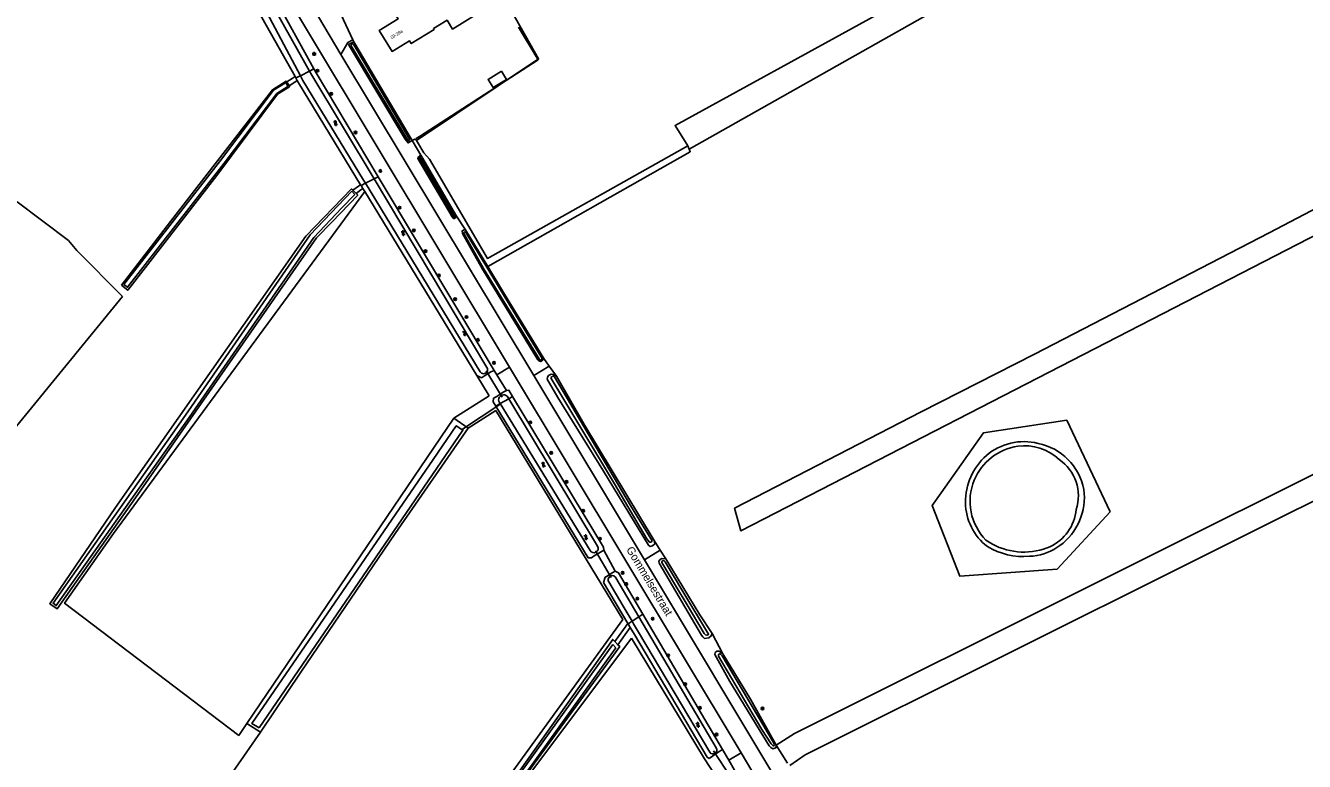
# Model space of a CAD drawing. Extents: x 137000 to 140001, y 403500 to 406000.
# Drawn here: x 138915.5 to 139315.1, y 404598.3 to 404828.4 of the extents above; entities that cross this region are included whole.
import ezdxf

# ---------------------------------------------------------------- set-up
doc = ezdxf.new("R2010")
doc.units = 0
for name, color, linetype in [('gg-afsc-draadraster', 7, 'Continuous'), ('gg-afsc-erfafscheiding', 7, 'Continuous'), ('gg-afsc-hekwerk', 7, 'Continuous'), ('gg-afsc-lijn draadraster', 7, 'Continuous'), ('gg-anno-huisnummerreeks BGT', 7, 'Continuous'), ('gg-anno-openbare ruimte label', 7, 'Continuous'), ('gg-bbg-hoofdgebouw', 7, 'Continuous'), ('gg-bbg-luifel en loopbrug', 7, 'Continuous'), ('gg-knt-bronhoudergrens', 7, 'Continuous'), ('gg-knt-onverhard', 7, 'Continuous'), ('gg-knt-verharding', 7, 'Continuous'), ('gg-knt-verharding nz', 7, 'Continuous'), ('gg-kntw-bovenkant insteek waterloop', 7, 'Continuous'), ('gg-kntw-waterlijn', 7, 'Continuous'), ('gg-kwrk-duiker nz buis', 7, 'Continuous'), ('gt-grn-groengrens', 7, 'Continuous'), ('gt-grn-groengrens NZ', 7, 'Continuous'), ('gt-grn-vlakafsluiter', 7, 'Continuous'), ('gt-grn-weggrens', 7, 'Continuous'), ('gt-symb-boom', 7, 'Continuous'), ('gt-symb-lichtmast', 7, 'Continuous'), ('gt-symb-watersymbool', 7, 'Continuous')]:
    doc.layers.add(name, color=color, linetype=linetype)

# ---------------------------------------------------------------- blocks, each defined once
blk = doc.blocks.new('gt0-BOOM')
at = {"layer": 'gt-symb-boom'}
for radius in [0.4, 0.2]:
    blk.add_circle((0, 0), radius, dxfattribs=at)
blk = doc.blocks.new('gt0-WA')
at = {"layer": 'gt-symb-watersymbool'}
for centre, start, end in [((-0.32, 0.02), 28.0725, 151.9275), ((0.43, 0.42), 208.0725, 331.9275), ((-0.32, -0.43), 28.0725, 151.9275), ((0.43, -0.03), 208.0725, 331.9275)]:
    blk.add_arc(centre, 0.425, start, end, dxfattribs=at)
blk = doc.blocks.new('gt0-LMAST')
at = {"layer": 'gt-symb-lichtmast'}
for p, q in [((-0.18, 0.17), (-0.45, 0.44)), ((-0.01, 0.25), (-0.01, 0.62)), ((0.17, 0.17), (0.44, 0.44)), ((-0.26, 0), (-0.63, 0)), ((-0.18, -0.18), (-0.45, -0.45)), ((-0.01, -0.25), (-0.01, -0.63)), ((0.44, -0.45), (0.17, -0.18)), ((0.24, 0), (0.62, 0))]:
    blk.add_line(p, q, dxfattribs=at)
blk.add_circle((-0.01, 0), 0.25, dxfattribs=at)

msp = doc.modelspace()

# ---------------------------------------------------------------- linework, layer by layer
at = {"layer": 'gg-afsc-draadraster'}
msp.add_line((138984.69, 404610.16), (138982.17, 404606.45), dxfattribs=at)
msp.add_lwpolyline([(139102.12, 404642.66), (139080.7, 404678.06), (139062.45, 404708.05)], dxfattribs=at)
at = {"layer": 'gg-afsc-erfafscheiding'}
for p, q in [((139018.1, 404823.32), (139017.74, 404823.94)), ((139103.71, 404641.47), (139099.63, 404635.81)), ((139104.48, 404640.16), (139100.63, 404634.79))]:
    msp.add_line(p, q, dxfattribs=at)
for points in [[(138999.75, 404812.46), (138998.86, 404811.88), (138997.11, 404810.74)], [(139000.44, 404811.23), (138999.62, 404810.7), (138997.86, 404809.56)], [(139020.22, 404778.64), (139019.51, 404778.14), (139017.76, 404776.88)]]:
    msp.add_lwpolyline(points, dxfattribs=at)
at = {"layer": 'gg-afsc-hekwerk'}
for p, q in [((139075.7, 404817.67), (139069.55, 404827.92)), ((139038.6, 404793.75), (139075.7, 404817.67)), ((139037.62, 404793.12), (139038.6, 404793.75))]:
    msp.add_line(p, q, dxfattribs=at)
at = {"layer": 'gg-afsc-lijn draadraster'}
for p, q in [((139049.39, 404705.6), (138984.69, 404610.16)), ((138984.69, 404610.16), (138982.17, 404606.45))]:
    msp.add_line(p, q, dxfattribs=at)
msp.add_lwpolyline([(139102.12, 404642.66), (139080.7, 404678.06), (139062.45, 404708.05)], dxfattribs=at)
at = {"layer": 'gg-bbg-hoofdgebouw'}
msp.add_lwpolyline([(139059.68, 404833.96), (139048.96, 404827.28), (139047.24, 404830.05), (139043, 404827.42), (139043.15, 404827.18), (139036.02, 404822.75), (139035.46, 404823.64), (139030.04, 404820.29), (139026.03, 404826.87), (139031.92, 404830.46), (139031.33, 404831.38), (139037.89, 404835.41), (139038.07, 404835.11), (139042.34, 404837.73)], dxfattribs=at)
at = {"layer": 'gg-bbg-luifel en loopbrug'}
msp.add_lwpolyline([(139064.22, 404814.11), (139060.04, 404811.56), (139061.6, 404809), (139065.78, 404811.55), (139064.22, 404814.11)], dxfattribs=at)
at = {"layer": 'gg-knt-bronhoudergrens'}
for p, q in [((139021.53, 404776.49), (138943, 404669.59)), ((139079.14, 404721.91), (139077.41, 404724.28)), ((139081.41, 404718.79), (139079.14, 404721.91)), ((139056.48, 404719.01), (139060.34, 404712.65)), ((139049.39, 404705.6), (139060.34, 404712.65)), ((139053.85, 404702.51), (139062.45, 404708.05)), ((139111.92, 404667.43), (139113.85, 404664.37)), ((139096.19, 404664.4), (139099.72, 404657.86)), ((139115.58, 404661.63), (139113.85, 404664.37)), ((139130.03, 404638.28), (139133.35, 404632.02)), ((139104.82, 404636.82), (139127.61, 404599.12)), ((139153.59, 404597.79), (139150.08, 404603.43))]:
    msp.add_line(p, q, dxfattribs=at)
for points in [[(139037.66, 404792.46), (139075.83, 404817.93), (139067.22, 404833.1), (139070.72, 404835.33), (139068.44, 404839.22), (139085.09, 404850.14), (139076.16, 404864.06), (139082.38, 404867.96), (139085.94, 404869.01), (139084.03, 404871.84), (139082.12, 404872.23), (139080.67, 404873.42), (139078.9, 404874.54), (139076.86, 404877.04), (139074.36, 404879.47), (139072.98, 404881.64), (139070.8, 404884.14), (139069.36, 404886.31), (139067.84, 404888.68), (139066.07, 404889.93), (139061.58, 404886.77), (139042.16, 404873.81)], [(139122.5, 404790.77), (139118.46, 404797.17), (139179.18, 404830.53), (139224.62, 404855.9), (139280.61, 404887.21)], [(139037.66, 404792.46), (139039.95, 404788.59), (139041.69, 404786.63), (139059.84, 404755.58), (139122.5, 404790.77)], [(138795.51, 404634.93), (138912.95, 404773.27), (138928.9, 404761.22), (138931.58, 404758.11), (138945.79, 404743.66)], [(138945.79, 404743.66), (138886.04, 404670.61), (138813.08, 404581.5), (138816.79, 404594.38), (138818.73, 404606.25), (138822.87, 404620.33), (138817.65, 404621.14), (138815, 404623.92)], [(139341.4, 404699.8), (139155.77, 404607.03), (139150.08, 404603.43)], [(139344.37, 404692.94), (139159.11, 404600.36), (139154.3, 404597.05)], [(138982.17, 404606.45), (138927.71, 404647.78), (138943, 404669.59)], [(139102.12, 404642.66), (139018.27, 404527.02), (139003.99, 404504.48)], [(139050.76, 404459.51), (139010.67, 404503.17), (139015.43, 404509.65), (139071.88, 404592.83), (139104.82, 404636.82)], [(139003.99, 404504.48), (138932.15, 404391.06), (138903.87, 404418.47), (138875.88, 404447.33), (138910.75, 404494.8), (138988.93, 404607.46)], [(139127.61, 404599.12), (139136.05, 404586.21), (139136.73, 404584.82)]]:
    msp.add_lwpolyline(points, dxfattribs=at)
at = {"layer": 'gg-knt-onverhard'}
msp.add_lwpolyline([(139018.78, 404775.89), (139020.33, 404777), (139020.95, 404777.44)], dxfattribs=at)
at = {"layer": 'gg-knt-verharding'}
for p, q in [((139013.37, 404833.3), (139017.74, 404823.94)), ((139014.07, 404819.36), (139074.31, 404719.01)), ((139139.1, 404601.02), (139066.78, 404721.54)), ((139074.31, 404719.01), (139108.89, 404661.39)), ((139152.21, 404589.23), (139108.89, 404661.39)), ((139208.68, 404485.07), (139139.1, 404601.02))]:
    msp.add_line(p, q, dxfattribs=at)
for points in [[(139066.78, 404721.54), (138961.66, 404896.8), (138938.92, 404934.88), (138927.44, 404953.75), (138924.75, 404958.01)], [(139017.74, 404823.94), (139016.24, 404823.05), (139014.07, 404819.36)]]:
    msp.add_lwpolyline(points, dxfattribs=at)
at = {"layer": 'gg-knt-verharding nz'}
msp.add_line((139007.02, 404831.11), (139014.07, 404819.36), dxfattribs=at)
at = {"layer": 'gg-kntw-bovenkant insteek waterloop'}
for p, q in [((139005.62, 404814.86), (138990.01, 404843.14)), ((138999.75, 404812.46), (138984.55, 404839.53)), ((139018.1, 404823.32), (139036.3, 404792.45)), ((138997.86, 404809.56), (138997.11, 404810.74)), ((138999.75, 404812.46), (139000.01, 404812)), ((139000.44, 404811.23), (139000.01, 404812)), ((139000.44, 404811.23), (139000.85, 404810.5)), ((139020.22, 404778.64), (139000.85, 404810.5)), ((139050.18, 404768.75), (139039.29, 404787.35)), ((139020.22, 404778.64), (139020.37, 404778.39)), ((139020.95, 404777.44), (139020.37, 404778.39)), ((139025.74, 404781.12), (139061.96, 404720.57)), ((139018.78, 404775.89), (139017.76, 404776.88)), ((139021.53, 404776.49), (139020.95, 404777.44)), ((139056.48, 404719.01), (139021.53, 404776.49)), ((139053.02, 404764.55), (139059.99, 404753.02)), ((139057.99, 404718.27), (139056.48, 404719.01)), ((139064.8, 404713.73), (139062.76, 404712.47)), ((139065.75, 404714.32), (139064.8, 404713.73)), ((139049.39, 404705.6), (138984.69, 404610.16)), ((139053.85, 404702.51), (139049.39, 404705.6)), ((139093.17, 404662.58), (139095.14, 404663.76)), ((139095.14, 404663.76), (139096.19, 404664.4)), ((139230.39, 404662.51), (139229.17, 404662.47)), ((139099.04, 404657.41), (139099.72, 404657.86)), ((139103.71, 404641.47), (139096.11, 404654.3)), ((139099.04, 404657.41), (139096.99, 404656.18)), ((139133.32, 404602.1), (139108.44, 404644.35)), ((139103.79, 404641.33), (139103.71, 404641.47)), ((139104.48, 404640.16), (139103.79, 404641.33)), ((139099.63, 404635.81), (139100.63, 404634.79)), ((138984.69, 404610.16), (138988.93, 404607.46)), ((139133.32, 404602.1), (139131.97, 404601.19)), ((139128.46, 404599.66), (139129.17, 404599.3)), ((139131.97, 404601.19), (139129.17, 404599.3))]:
    msp.add_line(p, q, dxfattribs=at)
for points in [[(139018.1, 404823.32), (139016.43, 404822.44), (139034.13, 404792.9), (139035.07, 404791.72), (139036.3, 404792.45)], [(139005.62, 404814.86), (139006.32, 404813.58), (139025.74, 404781.12)], [(138997.11, 404810.74), (138996.92, 404811.03), (138992.64, 404808.3), (138960.83, 404767.13), (138945.52, 404747.21)], [(138945.52, 404747.21), (138947.46, 404745.66), (138975.28, 404781.49), (138994.27, 404806.89), (138998.03, 404809.28), (138997.86, 404809.56)], [(139050.18, 404768.75), (139049.94, 404768.33), (139049.34, 404768.01), (139048.82, 404768.55), (139038.09, 404786.79), (139038.16, 404787.25), (139038.6, 404787.67), (139039.29, 404787.35)], [(139017.76, 404776.88), (139017.32, 404777.3), (139003.12, 404762.57), (138943.62, 404677.69), (138923.09, 404647.63), (138925.37, 404646), (138930.14, 404652.66), (138949.91, 404680.74), (139006.48, 404762), (139011.19, 404766.89)], [(139011.19, 404766.89), (139019.34, 404775.35), (139018.78, 404775.89)], [(139077.41, 404724.28), (139077.07, 404723.76), (139076.5, 404723.34), (139075.85, 404723.62), (139075.62, 404723.92), (139058.28, 404752.26), (139052.01, 404763.39), (139051.93, 404764.21), (139052.56, 404764.5), (139053.02, 404764.55)], [(139077.41, 404724.28), (139065.17, 404744.43), (139059.99, 404753.02)], [(139061.96, 404720.57), (139060.95, 404720.09), (139058.9, 404718.85), (139057.99, 404718.27)], [(139081.41, 404718.79), (139080.57, 404719.34), (139079.78, 404719.43), (139078.94, 404718.95), (139078.6, 404718.43), (139078.55, 404717.87), (139081.88, 404712.07), (139096.11, 404689.03), (139110.13, 404665.92), (139110.65, 404665.58), (139111.41, 404665.73), (139112.09, 404666.37), (139111.92, 404667.43)], [(139081.41, 404718.79), (139089.98, 404703.91), (139111.92, 404667.43)], [(139065.75, 404714.32), (139066.57, 404714.35), (139067.72, 404712.42)], [(139062.43, 404709.39), (139061.62, 404710.72), (139061.73, 404711.86), (139062.76, 404712.47)], [(139067.72, 404712.42), (139096.06, 404665.27), (139096.19, 404664.4)], [(139062.43, 404709.39), (139091.36, 404661.95), (139092.33, 404661.98), (139093.17, 404662.58)], [(138988.93, 404607.46), (139001.53, 404626.2), (139030.99, 404669.56), (139053.85, 404702.51)], [(139130.03, 404638.28), (139129.78, 404637.59), (139128.97, 404636.95), (139127.68, 404636.75), (139127.19, 404637.26), (139126.75, 404637.86), (139113.53, 404660.32), (139113.38, 404660.95), (139113.76, 404661.44), (139114.36, 404661.75), (139115.58, 404661.63)], [(139130.03, 404638.28), (139126.24, 404644.15), (139115.58, 404661.63)], [(139099.72, 404657.86), (139100.79, 404657.33), (139108.44, 404644.35)], [(139096.99, 404656.18), (139096.62, 404655.93), (139096.11, 404654.3)], [(139104.48, 404640.16), (139105.78, 404637.97), (139128.46, 404599.66)], [(139100.63, 404634.79), (139101.16, 404634.25), (139074.59, 404597.78), (139040.61, 404549.81), (139014.58, 404513), (139005.96, 404502.08), (139003.86, 404503.74)], [(139004.08, 404504.41), (139012.76, 404515.49), (139036.47, 404549.18), (139061.95, 404584.18), (139098.99, 404636.46), (139099.63, 404635.81)], [(139150.08, 404603.43), (139149.93, 404602.57), (139149.03, 404602.3), (139148.41, 404602.67), (139147.9, 404603.22), (139135.59, 404623.3), (139130.86, 404631.78), (139131.04, 404632.34), (139131.55, 404632.82), (139132.28, 404632.8), (139133.35, 404632.02)], [(139150.08, 404603.43), (139142.03, 404617.77), (139133.35, 404632.02)]]:
    msp.add_lwpolyline(points, dxfattribs=at)
for centre, radius, start, end in [((139227.46, 404680.3), 18.01, 75.7922, 130.6077), ((139228.29, 404679.86), 18.26, 11.098, 78.6506), ((139228.27, 404679.65), 19.03, 131.1605, 181.2681), ((139227.52, 404680.99), 18.84, 306.3597, 7.2818), ((139226.35, 404679.23), 17.12, 180.0153, 233.1449), ((139228.22, 404680.03), 17.66, 277.0746, 306.3782), ((139227.28, 404683.84), 21.45, 238.5393, 275.0368)]:
    msp.add_arc(centre, radius, start, end, dxfattribs=at)
at = {"layer": 'gg-kntw-waterlijn'}
for p, q in [((138988.59, 404842.07), (139004.27, 404814.17)), ((138986.43, 404840.98), (139001.39, 404812.71)), ((139017.26, 404822.02), (139034.93, 404792.54)), ((139035.46, 404792.9), (139018.1, 404822.35)), ((138996.79, 404810.53), (138996.9, 404810.6)), ((138996.9, 404810.6), (138997.51, 404809.33)), ((138994.01, 404807.14), (138997.51, 404809.33)), ((139021.71, 404779.07), (139057.53, 404720.16)), ((139024.4, 404780.44), (139059.69, 404721.45)), ((139017.43, 404776.65), (139018.36, 404775.59)), ((138966.65, 404705.81), (139005.57, 404762.12)), ((139063.82, 404710.19), (139063.57, 404710.59)), ((139063.82, 404710.19), (139091.93, 404664.23)), ((139066.22, 404712.21), (139066.51, 404711.73)), ((139066.51, 404711.73), (139094.27, 404665.66)), ((139233.56, 404664.72), (139235.54, 404665.41)), ((139107.18, 404643.53), (139099.96, 404655.78)), ((139107.18, 404643.53), (139131.31, 404602.56)), ((139055.11, 404573.87), (139099, 404634.93)), ((139056.25, 404573.05), (139099.95, 404633.85)), ((139099, 404634.93), (139099.95, 404633.85))]:
    msp.add_line(p, q, dxfattribs=at)
for points in [[(139004.27, 404814.17), (139005.02, 404812.83), (139024.4, 404780.44)], [(138996.79, 404810.53), (138993.04, 404808.19), (138976.42, 404786.18), (138946.27, 404747.46), (138947.38, 404746.6), (138977.53, 404785.33), (138994.01, 404807.14)], [(139001.39, 404812.71), (139002.2, 404811.17), (139021.13, 404780.03), (139021.28, 404779.79), (139021.71, 404779.07)], [(139038.68, 404787.19), (139038.54, 404787.05), (139038.51, 404786.86), (139049.14, 404768.8), (139049.42, 404768.51), (139049.65, 404768.63), (139049.72, 404768.75), (139039.01, 404787.04), (139038.68, 404787.19)], [(139017.43, 404776.65), (139004.48, 404763), (138965.51, 404706.63)], [(139005.57, 404762.12), (139014.26, 404771.27), (139018.36, 404775.59)], [(139052.47, 404763.37), (139058.63, 404752.47), (139075.95, 404724.15), (139076.1, 404723.94), (139076.45, 404723.8), (139076.78, 404724.04), (139076.94, 404724.28), (139064.83, 404744.22), (139059.65, 404752.81), (139053.07, 404763.7)], [(139079.66, 404718.36), (139079.91, 404718.6), (139080.22, 404718.83), (139080.76, 404718.57), (139104.58, 404678.3), (139111.29, 404667.3), (139111.24, 404667.16), (139111.05, 404666.95), (139110.97, 404666.9), (139110.71, 404666.84), (139110.46, 404666.93), (139109.69, 404667.94), (139099.49, 404685.1), (139083.76, 404711.46), (139079.75, 404718.03), (139079.66, 404718.36)], [(138965.51, 404706.63), (138924.1, 404647.77), (138925.09, 404647.04), (138966.65, 404705.81)], [(138988.53, 404608.85), (138986.25, 404610.15), (139042.85, 404692.77), (139050.08, 404703.28), (139052.19, 404701.91), (138988.53, 404608.85)], [(139127.57, 404638.28), (139128.01, 404637.89), (139128.4, 404637.78), (139128.82, 404637.95), (139128.94, 404638.13), (139120.93, 404651.44), (139115.37, 404660.76), (139115.05, 404661.04), (139114.78, 404661.14), (139114.48, 404660.98), (139114.3, 404660.8), (139114.29, 404660.51), (139118.56, 404653.32), (139122.2, 404647.3), (139127.57, 404638.28)], [(139105.05, 404642.15), (139102.26, 404646.86), (139097.74, 404654.49)], [(139105.05, 404642.15), (139105.49, 404641.39), (139105.49, 404641.39), (139107.07, 404638.73), (139129.29, 404601.19)], [(139149.48, 404603.48), (139148.87, 404604.77), (139133.16, 404631.4), (139132.68, 404631.84), (139132.42, 404631.98), (139132.16, 404631.84), (139131.99, 404631.55), (139132, 404631.27), (139145.58, 404608.35), (139148.53, 404603.84), (139148.97, 404603.35), (139149.2, 404603.18), (139149.4, 404603.34), (139149.48, 404603.48)]]:
    msp.add_lwpolyline(points, dxfattribs=at)
for centre, radius, start, end in [((139017.68, 404822.19), 0.449, 19.6366, 202.2826), ((139035.21, 404792.69), 0.322, 207.7708, 40.8029), ((139052.77, 404763.53), 0.342, 29.8826, 208.2754), ((139058.61, 404720.8), 1.26, 210.6434, 30.6899), ((139064.89, 404711.4), 1.55, 31.4286, 211.4305), ((139227.99, 404679.67), 17.36, 98.177, 157.5344), ((139227.74, 404681.51), 15.51, 46.2756, 98.2463), ((139230.72, 404681.33), 13.77, 341.9606, 55.8028), ((139228.05, 404679.68), 17.42, 157.6132, 224.371), ((139229.28, 404678.63), 14.63, 295.3414, 353.8339), ((139093.1, 404664.94), 1.37, 211.3899, 31.3604), ((139227.41, 404684.41), 20.62, 235.0778, 287.3627), ((139098.85, 404655.14), 1.28, 29.9608, 209.9936), ((139130.3, 404601.88), 1.22, 214.0869, 34.0618)]:
    msp.add_arc(centre, radius, start, end, dxfattribs=at)
at = {"layer": 'gg-kwrk-duiker nz buis'}
for p, q in [((139059.46, 404720.48), (139064.41, 404712.17)), ((139051.75, 404701.97), (139064, 404710.1)), ((139098.55, 404655.86), (139093.64, 404664.16)), ((139130.44, 404601.61), (139135.76, 404593.48))]:
    msp.add_line(p, q, dxfattribs=at)
at = {"layer": 'gt-grn-groengrens'}
for p, q in [((139037.36, 404792.99), (139036.3, 404792.45)), ((139122.5, 404790.77), (139122.89, 404789.75))]:
    msp.add_line(p, q, dxfattribs=at)
for points in [[(139307.78, 404894.04), (139235.46, 404853.42), (139122.89, 404789.75)], [(139368.88, 404788.8), (139271, 404738.4), (139139.01, 404670.43), (139137.04, 404677.51), (139195.33, 404707.61), (139230.72, 404725.69), (139304.13, 404763.6), (139365.11, 404795.56)], [(139122.89, 404789.75), (139123.2, 404788.92), (139059.99, 404753.02)], [(139254.45, 404676.38), (139237.87, 404658.48), (139207.49, 404656.21), (139198.79, 404678.37), (139201.64, 404682.26), (139214.79, 404701.06), (139240.87, 404705.01), (139254.45, 404676.38)]]:
    msp.add_lwpolyline(points, dxfattribs=at)
at = {"layer": 'gt-grn-groengrens NZ'}
for p, q in [((139036.3, 404792.45), (139039.29, 404787.35)), ((139050.18, 404768.75), (139053.02, 404764.55)), ((139062.82, 404719.16), (139061.96, 404720.57)), ((139062.82, 404719.16), (139065.75, 404714.32)), ((139135.28, 404598.73), (139133.32, 404602.1)), ((139135.28, 404598.73), (139137.07, 404595.65))]:
    msp.add_line(p, q, dxfattribs=at)
at = {"layer": 'gt-grn-vlakafsluiter'}
for p, q in [((139001.39, 404812.71), (139004.27, 404814.17)), ((139004.27, 404814.17), (139005.62, 404814.86)), ((139001.39, 404812.71), (139000.01, 404812)), ((139037.66, 404792.46), (139037.36, 404792.99)), ((139021.71, 404779.07), (139020.37, 404778.39)), ((139024.4, 404780.44), (139021.71, 404779.07)), ((139024.4, 404780.44), (139025.74, 404781.12)), ((139062.43, 404709.39), (139063.82, 404710.19)), ((139063.82, 404710.19), (139066.51, 404711.73)), ((139066.51, 404711.73), (139067.72, 404712.42)), ((139103.79, 404641.33), (139105.05, 404642.15)), ((139107.18, 404643.53), (139105.05, 404642.15)), ((139108.44, 404644.35), (139107.18, 404643.53))]:
    msp.add_line(p, q, dxfattribs=at)
at = {"layer": 'gt-grn-weggrens'}
for p, q in [((139066.78, 404721.54), (139062.82, 404719.16)), ((139074.31, 404719.01), (139079.14, 404721.91)), ((139113.85, 404664.37), (139108.89, 404661.39)), ((139139.1, 404601.02), (139135.28, 404598.73))]:
    msp.add_line(p, q, dxfattribs=at)

# ---------------------------------------------------------------- block references
at = {"layer": 'gt-symb-boom'}
for p in [(139006.76, 404814.29), (139011.02, 404807.03), (139018.62, 404794.95), (139026.38, 404782.94), (139032.4, 404771.47), (139036.85, 404764.34), (139040.48, 404757.86), (139044.65, 404750.26), (139049.74, 404742.83), (139053.29, 404737.28), (139056.85, 404730.11), (139061.9, 404722.94), (139073.27, 404704.35), (139079.78, 404694.81), (139084.53, 404685.75), (139089.76, 404676.68), (139094.99, 404667.99), (139102.09, 404657.3), (139106.66, 404649.24), (139111.47, 404642.94), (139116.33, 404631.49), (139121.62, 404622.51), (139126.19, 404615.11), (139145.8, 404614.9), (139131.42, 404606.75)]:
    msp.add_blockref('gt0-BOOM', p, dxfattribs=at)
at = {"layer": 'gt-symb-lichtmast'}
for p in [(139005.72, 404819.52), (139103.17, 404653.8)]:
    msp.add_blockref('gt0-LMAST', p, dxfattribs=at)
at = {"layer": 'gt-symb-watersymbool'}
for p, rotation in [((139012.4, 404797.85), 126.99589775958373), ((139033.52, 404763.44), 126.9958977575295), ((139052.75, 404732.15), 126.99589775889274), ((139077.35, 404691.07), 126.9958977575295), ((139090.65, 404668.37), 126.99589775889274), ((139125.62, 404609.74), 126.9958977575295)]:
    msp.add_blockref('gt0-WA', p, dxfattribs=dict(at, rotation=rotation))

# ---------------------------------------------------------------- texts
at = {"layer": 'gg-anno-huisnummerreeks BGT'}
msp.add_text('28-28a', height=1, rotation=31.4, dxfattribs=at).set_placement((139029.86, 404824.1))
at = {"layer": 'gg-anno-openbare ruimte label'}
msp.add_text('Gommelsestraat', height=2.5, rotation=301, dxfattribs=at).set_placement((139103.11, 404664.59))

doc.saveas('drawing.dxf')
